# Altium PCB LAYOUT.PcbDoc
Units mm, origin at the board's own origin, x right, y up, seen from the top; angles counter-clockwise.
Board outline 137.2 x 16.05 mm, 2 copper layers (Top Layer, Bottom Layer), stack 0.871 mm thick; 22 components, 24 nets, 86 pads, 18 vias.
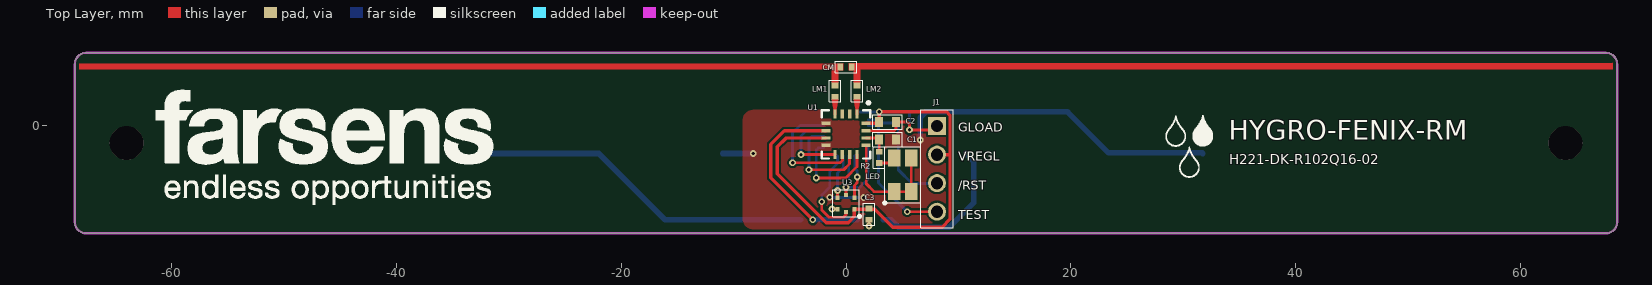
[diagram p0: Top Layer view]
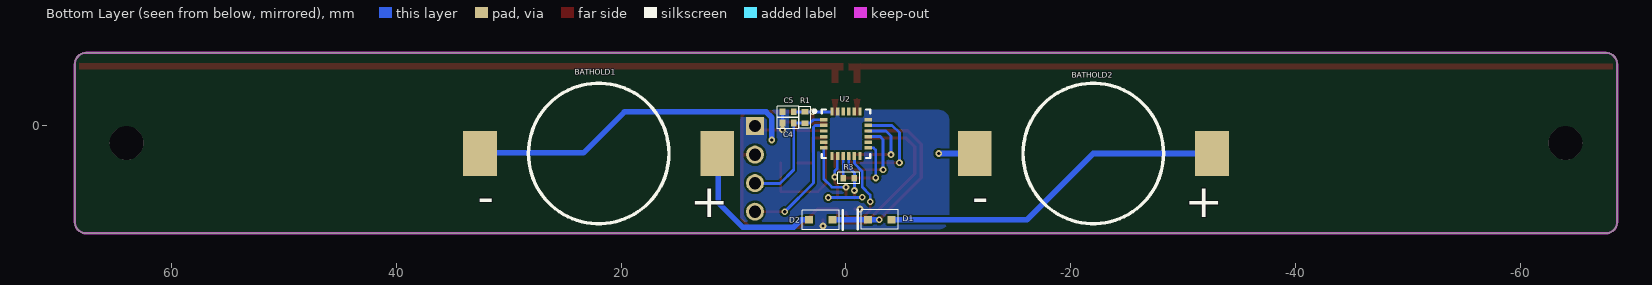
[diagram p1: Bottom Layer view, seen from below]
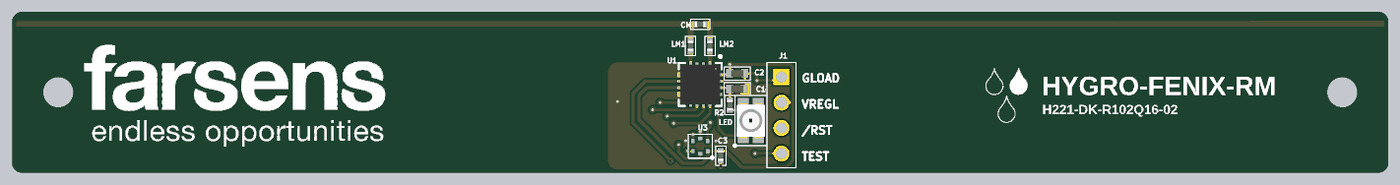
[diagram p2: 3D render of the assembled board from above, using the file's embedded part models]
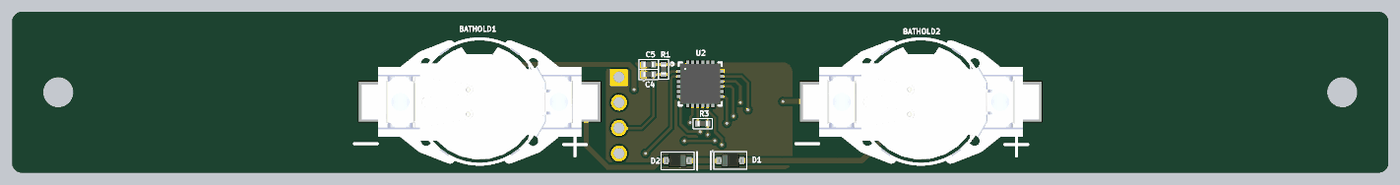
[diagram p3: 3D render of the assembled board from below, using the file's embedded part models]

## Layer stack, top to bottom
Top Solder: solder mask 0.0102, Solder Resist, Dk 3.5
Top Layer: signal copper 0.0356
Dielectric1: core 0.8, FR-4, Dk 4.8
Bottom Layer: signal copper 0.0356
Bottom Solder: solder mask 0.0102, Solder Resist, Dk 3.5

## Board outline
-67.6,-9.6 cw(c-67.6,-8.6) -68.6,-8.6 -68.6,5.45 cw(c-67.6,5.45) -67.6,6.45 67.6,6.45 cw(c67.6,5.45) 68.6,5.45 68.6,-8.6 cw(c67.6,-8.6) 67.6,-9.6

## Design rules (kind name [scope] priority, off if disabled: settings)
Clearance [All] p1: gap=0.2 ignorepadtopadclearanceinfootprint=FALSE except(0: Arc-Hole Track-Hole SMDPad-Hole THPad-Hole Via-Hole Fill-Hole Poly-Hole Region-Hole Text-Hole)
ComponentClearance [All] p1: gap=0.2 collisioncheckmode=3 verticalgap=0.2 showdistances=FALSE
HoleSize [All] p1: absolutevalues=TRUE maxlimit=3 minlimit=0.025 maxpercent=80.000 minpercent=20.000
HoleToHoleClearance [All] p1: gap=0.2 allowstackedmicrovias=TRUE
MinimumSolderMaskSliver [All] p1: minsoldermaskwidth=0.1
PlaneClearance [All] p1: clearance=1
PlaneConnect [All] p1: planeconnectstyle=Relief reliefexpansion=0.5 reliefentries=4 reliefconductorwidth=0.25 reliefairgap=0.5
PolygonConnect [All] p1: connectstyle=Direct reliefconductorwidth=0.5 reliefentries=4 polygonreliefangle="90 Angle" airgapwidth=0.254
RoomDefinition SCHEMATIC [InComponentClass('SCHEMATIC')] p1: confinementstyle=ConfineIn formatcopy=TRUE lockcomponents=FALSE outline -70.1,-13.15 72.95,-13.15 72.95,8 -70.1,8
RoutingCorners [All] p1: cornerstyle=45-Degree minsetback=2.5 maxsetback=2.5
RoutingVias [All] p1: holewidth=0.711 width=1.27 viastyle="Through Hole" minholewidth=0.2 minwidth=0.4 maxholewidth=3 maxwidth=5
SilkToSilkClearance [All] p1: silktosilkclearance=0.1
SilkToSolderMaskClearance SilkscreenOverComponentPads [IsPad] p1: minsilkscreentomaskgap=0.05 clearancetoexposedcopper=TRUE
SolderMaskExpansion [All] p1: expansion=0.1
Width [All] p1: maxlimit=3 minlimit=0.1 preferedwidth=0.25 bottomlayer_minwidth=0.2 minimp=50.000000 maximp=50.000000 favimp=50.000000
21 further rules are at their usual default settings.

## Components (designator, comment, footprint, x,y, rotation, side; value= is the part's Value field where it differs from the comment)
BATHOLD1 "SMTU1225-LF" SMTU1225-LF 22,-2.5 r0 bottom
BATHOLD2 "SMTU1225-LF" SMTU1225-LF -22,-2.5 r0 bottom
C1 "Capacitor" "LCR 0603 (1608)" 3.7,-1.25 r0 top
C2 "Capacitor" "LCR 0603 (1608)" 3.7,0.3 r0 top
C3 "Capacitor" "LCR 0402 (1005)" 2.05,-7.9 r270 top
C4 "Capacitor" "LCR 0402 (1005)" 5.15,0.2 r0 bottom
C5 "Capacitor" "LCR 0402 (1005)" 5.15,1.2 r0 bottom
CM "Capacitor" "LCR 0402 (1005)" 0,5.2 r0 top
D1 "RB751V40,115" RB751V40,115 -3,-8.4 r180 bottom
D2 "RB751V40,115" RB751V40,115 2.25,-8.4 r0 bottom
HYGRO-FENIX-RM "BOARD_NAME" BOARD_NAME 35.6,-5.8 r90 top
J1 "Header No.4" "HEADER NO.4" 8.1,-3.87 r270 top
LED "ASMT-SGB5-NW703" ASMT-SGB5-NW703 5.05,-4.4 r0 top
LM1 "Inductor" "LCR 0402 (1005)" -0.975,3.05 r90 top
LM2 "Inductor" "LCR 0402 (1005)" 0.975,3.05 r90 top
R1 "Resistor" "LCR 0402 (1005)" 3.65,0.7 r90 bottom
R2 "Resistor" "LCR 0402 (1005)" 2.95,-2.85 r270 top
R3 "Resistor" "LCR 0402 (1005)" -0.25,-4.7 r0 bottom
U1 "R102" R102 0,-0.8 r270 top
U2 "MSP430FR2433IRGET" MSP430FR2433IRGET 0,-0.75 r180 bottom
U3 "HTS221" HTS221 0,-6.95 r180 top
? "Comment" "LOGO NEW MEDIUM" -46.9,-1.6 r0 top

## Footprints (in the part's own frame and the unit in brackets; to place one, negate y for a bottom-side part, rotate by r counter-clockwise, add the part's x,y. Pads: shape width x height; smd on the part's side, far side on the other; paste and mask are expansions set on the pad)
ASMT-SGB5-NW703 [mm] "PLCC-4, Body 3.2mmx2.8mm"
  rect 1.1x1.5 smd: A(-0.75,1.5) C(-0.75,-1.5) C(0.75,-1.5) C(0.75,1.5)
  silkscreen extent -1.7,-2.6 1.6,2.5, body extent -1.4,-1.75 1.4,1.75, height 1.95
BOARD_NAME [mm] "BOARD_NAME"
"HEADER NO.4" [mm] "Header 1-Row, 4-Pin, Pitch 2.54mm"
  rect 1.6x1.6 hole 1.1: 1(-3.81,0)
  round 1.6 hole 1.1: 2(-1.27,0) 3(1.27,0) 4(3.81,0)
  silkscreen extent -5.27,-1.45 5.25,1.45
HTS221 [mm] "HLGA-6L (2 x 2 x 0.9 mm)"
  rect 0.35x0.4 smd mask+0.025: 1(-0.75,0.5) 2(-0.75,-0.5) 4(0.75,-0.5) 5(0.75,0.5)
  rect 0.4x0.35 smd mask+0.025: 3(0,-0.75) 6(0,0.75)
  silkscreen extent -1.3,-1.2 1.2,1.25, body extent -1,-1 1,1, height 0.9
"LCR 0402 (1005)" [mm] "CASE 0402, Body 1mm x 0.5mm"
  rect 0.5x0.6 smd: 1(-0.5,0) 2(0.5,0)
  silkscreen extent -0.97,-0.51 0.97,0.51, body extent -0.5,-0.25 0.5,0.25, height 0.35
"LCR 0603 (1608)" [mm] "CASE 0603, Body 1.6mm x 0.8mm"
  rect 0.7x0.9 smd: 1(-0.75,0) 2(0.75,0)
  silkscreen extent -1.3,-0.65 1.3,0.65, body extent -0.76,-0.38 0.76,0.38, height 0.75
"LOGO NEW MEDIUM" [mm] "LOGO"
  silkscreen extent -14.5,-5.4 15.5,4.76
MSP430FR2433IRGET [mm] "QFN, 24-Leads, Body 4,00x4,00mm, Pitch 0,50mm,"
  rect 0.7x0.3 smd mask+0.1: 1(-1.975,1.25) 2(-1.975,0.75) 3(-1.975,0.25) 4(-1.975,-0.25) 5(-1.975,-0.75) 6(-1.975,-1.25) 13(1.975,-1.25) 14(1.975,-0.75) 15(1.975,-0.25) 16(1.975,0.25) 17(1.975,0.75) 18(1.975,1.25)
  rect 0.3x0.7 smd mask+0.1: 7(-1.25,-1.975) 8(-0.75,-1.975) 9(-0.25,-1.975) 10(0.25,-1.975) 11(0.75,-1.975) 12(1.25,-1.975) 19(1.25,1.975) 20(0.75,1.975) 21(0.25,1.975) 22(-0.25,1.975) 23(-0.75,1.975) 24(-1.25,1.975)
  silkscreen extent -2.93,-2.15 2.15,2.15, body extent -2,-2 2,2, height 0.9
R102 [mm] "QFN, 16-Leads, Body 4,00x4,00mm, Pitch 0,65mm,"
  rect 0.8x0.3 smd: 1(-1.8,0.975) 2(-1.8,0.325) 3(-1.8,-0.325) 4(-1.8,-0.975) 9(1.8,-0.975) 10(1.8,-0.325) 11(1.8,0.325) 12(1.8,0.975)
  rect 0.3x0.8 smd: 5(-0.975,-1.8) 6(-0.325,-1.8) 7(0.325,-1.8) 8(0.975,-1.8) 13(0.975,1.8) 14(0.325,1.8) 15(-0.325,1.8) 16(-0.975,1.8)
  silkscreen extent -2.92,-2.15 2.15,2.15, body extent -2,-2 2,2, height 0.92
RB751V40,115 [mm] "SOD 323 (SC-76)2.7mm x 1.35mm"
  rect 0.7x0.7 smd: 1(-1.05,0) 2(1.05,0)
  silkscreen extent -1.95,-0.85 1.65,0.9, body extent -1.3,-0.68 1.3,0.67, height 1.1
SMTU1225-LF [mm] "Battery holder, CR1225 coin cell"
  rect 3x4 smd: 1(-10.55,0) 2(10.55,0)
  silkscreen extent -6.25,-6.25 6.25,6.25, body extent -11.78,-6.12 11.76,6.2, height 5.03

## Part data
BATHOLD1 BATHOLD2: "Battery holder", 03 Value=CR1225, 06 Manufacturer=RENATA
C1: 03 Value=22uF, 06 Manufacturer=AVX, 07 Manufacturer Reference=06036D226MAT2A
C2: 03 Value=1uF, 06 Manufacturer=MURATA, 07 Manufacturer Reference=GRM188R71C105KA12D
C3 C5: 03 Value=100nF, 06 Manufacturer=MURATA, 07 Manufacturer Reference=GRM155R71C104KA88D
C4: 03 Value=1nF, 06 Manufacturer=MURATA, 07 Manufacturer Reference=GRM155R71H102KA01D
CM: 03 Value=1pF, 06 Manufacturer="Johanson Dielectrics", 07 Manufacturer Reference=500R07S1R0BV4T
D1 D2: "Schottky Diode", 06 Manufacturer=NXP
HYGRO-FENIX-RM: "LOGO FARSENS", 06 Manufacturer=Farsens
J1: "1-Row, 4-Pin, Pitch 2.54mm", 06 Manufacturer=Harwin, 07 Manufacturer Reference=M20-9770442
LED: "RGB triple LED", 03 Value=GREEN, 06 Manufacturer=AVAGO
LM1 LM2: 03 Value=36nH, 06 Manufacturer=MURATA, 07 Manufacturer Reference=LQW15AN36NG00D
R1 R3: 03 Value=10K, 06 Manufacturer=PANASONIC, 07 Manufacturer Reference=ERJ-2RKF1002X
R2: 03 Value=1K, 06 Manufacturer=SUSUMU, 07 Manufacturer Reference=RR0510P-102-D
U1: "RFID TAG", 06 Manufacturer=FARSENS, 07 Manufacturer Reference=R102Q16
U2: "Mixed-Signal Microcontroller", 06 Manufacturer="Silicon Labs"
U3: "HUMIDITY AND TEMPERATURE SENSOR", 06 Manufacturer="ST Microelectronics"

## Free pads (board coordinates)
  round 3 hole 3 unplated mask+0: ""(-64,-1.575) ""(64,-1.575)

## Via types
v1: diameter 0.6, hole 0.3, Top Layer to Bottom Layer, tented both sides, 18 vias

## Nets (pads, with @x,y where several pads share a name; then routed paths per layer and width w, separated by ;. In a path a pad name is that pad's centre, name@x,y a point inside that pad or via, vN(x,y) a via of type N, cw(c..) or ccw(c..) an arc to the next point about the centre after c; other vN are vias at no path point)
/RST: C4.1 J1.3 R1.1 U2.1 | length 10.9
  Bottom Layer w0.25: U2.1 2.889,0.5 3.189,0.2 R1.1 C4.1 4.65,-3.95 5.867,-5.167 J1.3@8.098,-5.167
CLK: U2.8 U3.2 | length 3.9
  Top Layer w0.25: U3.2 0.75,-5.35 1,-5.1 v1(1,-4.6)
  Bottom Layer w0.25: U2.8 0.775,-2.75 0.775,-3.825 1,-4.05 v1(1,-4.6)
CS: U2.11 U3.6 | length 8.2
  Top Layer w0.25: v1(-2.15,-6.8) -2.15,-7.55 -1.525,-8.175 -0.225,-8.175 0,-7.95 U3.6
  Bottom Layer w0.25: v1(-2.15,-6.8) -2.15,-6.2 -1.45,-5.5 -1.45,-4.1 -0.75,-3.4 U2.11
DRDY: U2.6 U3.3 | length 5.8
  Top Layer w0.25: U3.3 v1(0,-5.5)
  Bottom Layer w0.25: v1(0,-5.5) 1.25,-5.5 1.975,-4.775 U2.6
GLOAD: C2.2 C3.2 C4.2 C5.2 J1.1 U1.15 U2.18 U2.23 U3.5 | length 10.4
  Top Layer w0.25: v1(-1.25,-7.45) U3.5 ; U1.15 4.283,-0.475 4.45,-0.308 4.45,0.2 C2.2@4.5,0.25 ; v1(2.05,-8.95) C3.2 ; C2.2 5.45,0.3 5.65,0.1 v1(5.65,-0.4) 7.76,-0.4 J1.1
  Bottom Layer w0.25: v1(5.65,-0.4) C4.2 ; C5.2 C4.2@5.65,0.25 ; C4.2 C4.2@5.65,0.25 ; C4.2 5.6,0.25 C4.2@5.65,0.25
IO0/MISO: U1.9 U2.16 | length 6.9
  Top Layer w0.25: v1(-4,-2.6) U1.9
  Bottom Layer w0.25: v1(-4,-2.6) -4,-0.95 -3.55,-0.5 U2.16
IO1/MOSI: U1.10 U2.17 | length 10.8
  Top Layer w0.25: v1(-4.75,-3.325) -0.525,-3.325 -0.325,-3.125 U1.10
  Bottom Layer w0.25: v1(-4.75,-3.325) -4.75,-0.65 -4.1,0 U2.17
IO2/SCK: U1.11 U2.15 | length 8.8
  Top Layer w0.25: v1(-3.3,-3.95) -0.2,-3.95 0.325,-3.425 U1.11
  Bottom Layer w0.25: v1(-3.3,-3.95) -3.3,-1.25 -3.05,-1 U2.15
IO3/CS: U1.12 U2.13 | length 8.3
  Top Layer w0.25: v1(-2.65,-4.675) -0.025,-4.675 0.975,-3.675 U1.12
  Bottom Layer w0.25: v1@-2.65,-4.65 -2.65,-2.2 -2.45,-2 U2.13
IO4: LED.C U1.13 | length 10.3
  Top Layer w0.25: U1.13 1.8,-5.2 2.5,-5.9 4.3,-5.9 5.8,-5.9 LED.C@5.8,-3.35
MISO: R3.1 U2.10 U3.4 | length 3.9
  Top Layer w0.25: U3.4 v1(-0.75,-5.8)
  Bottom Layer w0.25: v1(-0.75,-5.8) -0.75,-4.25 -0.25,-3.75 U2.10
MOSI: R3.2 U2.9 | length 2
  Bottom Layer w0.25: R3.2 U2.9
NetBATHOLD1_1: BATHOLD1.1 D2.2 | length 13.9
  Bottom Layer w0.5: D2.2 4,-8.4 4.65,-9.05 9.2,-9.05 11.35,-6.9 11.35,-3.2 BATHOLD1.1@10.65,-2.5
NetBATHOLD2_1: BATHOLD2.1 D1.2 | length 30.4
  Bottom Layer w0.5: BATHOLD2.1@-32.05,-2.5 -22,-2.5 -16.1,-8.4 D1.2
NetCM_1: CM.1 LM1.2
NetCM_2: CM.2 LM2.2
NetD1_1: D1.1 D2.1 U1.6 | length 17.6
  Top Layer w0.3: v1(-2.95,-8.4) -6.7,-4.65 -6.7,-1.7 -5.475,-0.475 U1.6
  Bottom Layer w0.5: v1(-2.95,-8.4) -2.81,-8.4 -2.805,-8.405 -2.8,-8.4 D1.1 D2.1@1,-8.4
NetLED_A: LED.A R2.2 | length 1.4
  Top Layer w0.25: R2.2 LED.A@4.3,-3.35
RFN: LM1.1 U1.4 | length 1.3
  Top Layer w0.3: U1.4 -0.975,2.3
RFP: LM2.1 U1.1 | length 0.8
  Top Layer w0.3: U1.1 0.975,1.8
TEST: J1.4 U2.2 | length 12.2
  Top Layer w0.25: v1(5.45,-7.68) J1.4
  Bottom Layer w0.254: U2.2 2.75,0 2.9,-0.15 2.9,-5.13 v1(5.45,-7.68)
VDD: C1.1 R2.1 U1.14 | length 2.3
  Top Layer w0.25: U1.14 C1.1@2.95,-1.125 ; R2.1 C1.1
VREGL: C2.1 C3.1 C5.1 J1.2 R1.2 U1.7 U1.16 U2.24 U3.1 | length 48.3
  Top Layer w0.25: 9.23,-2.6 9.25,-2.62
  Top Layer w0.3: U1.7 -5.325,-1.125 -6.1,-1.9 -6.1,-4.322 -1.772,-8.65 0.2,-8.65 0.75,-8.1 U3.1 2.55,-7.45 4.15,-9.05 8.55,-9.05 9.25,-8.35 9.25,-2.62 9.25,0.9 8.95,1.2 v1(2.95,1.2) C2.1 C2.1@2.95,0.2 ; U1.16 C2.1@2.925,0.175 ; J1.2 9.23,-2.6
  Bottom Layer w0.25: U2.24@1.275,1.2 v1(2.95,1.2) R1.2 C5.1@4.6,1.2
VSS: BATHOLD1.2 BATHOLD2.2 C1.2 U1.5 U1.8 | length 34.6
  Bottom Layer w0.25: v1(-1.45,-6.4) -1.425,-6.425 v1(1.575,-6.425)
  Bottom Layer w0.5: BATHOLD2.2@-10.95,-2.5 v1(-8.25,-2.5) ; v1(6.6,-1.3) 6.6,0.694 7.106,1.2 19.7,1.2 23.35,-2.45 31.7,-2.45 BATHOLD1.2@31.75,-2.5
pads on no net: U1.2 U1.3 U2.3 U2.4 U2.5 U2.7 U2.12 U2.14 U2.19 U2.20 U2.21 U2.22

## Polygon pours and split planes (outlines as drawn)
GLOAD on Bottom Layer "GLOAD" (solid, remove dead copper, pour order 6): -9.19,-8.25 -9.19,0.41 cw(c-8.2,0.41) -8.2,1.4 8.4,1.4 cw(c8.4,0.4) 9.4,0.4 9.4,-8.25 cw(c8.4,-8.25) 8.4,-9.25 -8.299,-9.25 cw(c-8.244,-8.304)
VSS on Top Layer "VSSS" (solid, remove dead copper, pour order 8): -9.19,-8.25 -9.19,0.41 cw(c-8.2,0.41) -8.2,1.4 8.4,1.4 cw(c8.4,0.4) 9.4,0.4 9.4,-8.25 cw(c8.4,-8.25) 8.4,-9.25 -8.299,-9.25 cw(c-8.244,-8.304)

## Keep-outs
Keep-Out Layer:
  the board outline again, w0.2

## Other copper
Top Layer:
  pour cut-out: -2.15,0.6 2.15,0.6 2.15,1.4 -2.15,1.4
  region net NetCM_2: 0.675,3.8 0.675,4.9 0.25,4.9 0.25,5.5 1.275,5.503 1.275,3.8
  region net NetCM_1: -68.2,5 -0.25,4.996 -0.25,5.504 -68.2,5.5
  region net NetCM_2: 0.25,4.996 68.2,5 68.2,5.55 0.25,5.503
  region net NetCM_1: -1.275,3.8 -1.275,5.503 -0.25,5.5 -0.25,4.9 -0.675,4.9 -0.675,3.8
  region net RFN: -1.275,2.3 -1.125,1.5 -0.825,1.5 -0.675,2.3
  region net RFP: 0.675,2.3 0.825,1.5 1.125,1.5 1.275,2.3

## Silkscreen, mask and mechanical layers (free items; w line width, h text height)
Top Overlay:
  drawing of 599 lines, arcs and shapes, not listed
  text "GLOAD" at 10,-0.55 h0.8
  text "VREGL" at 10,-3.15 h0.8
  text "/RST" at 10,-5.75 h0.8
  text "TEST" at 10,-8.35 h0.8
